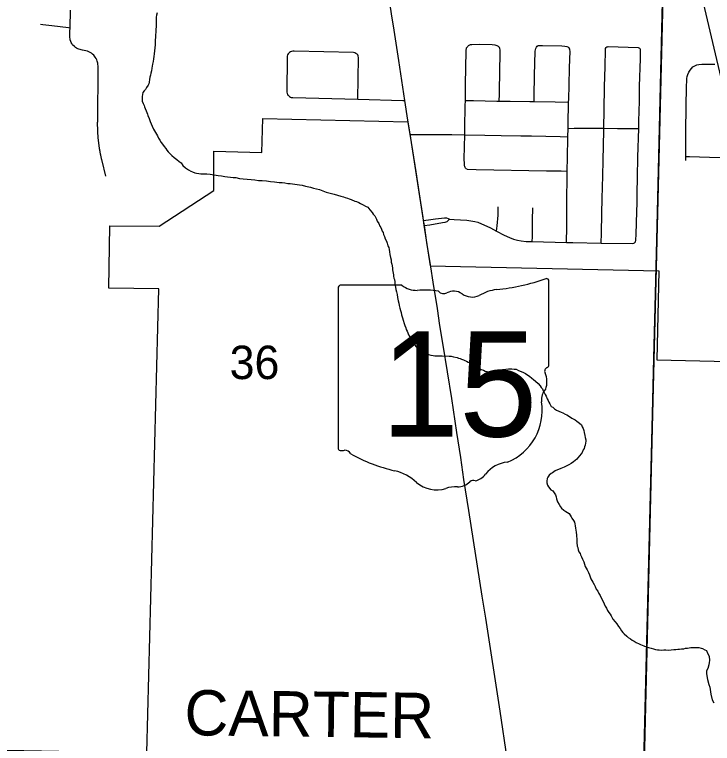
# Model space of a CAD drawing. Extents: x 0 to 34, y 0 to 22.
# Drawn here: x 6.597 to 7.471, y 16.393 to 17.306 of the extents above; entities that cross this region are included whole.
import ezdxf

# ---------------------------------------------------------------- set-up
doc = ezdxf.new("R2010")
doc.units = 0
for name, color, linetype in [('Default', 7, 'Continuous'), ('GM_X_City_Street', 7, 'Continuous'), ('GM_X_County_Road_Text', 7, 'Continuous'), ('GM_X_Minor_River', 7, 'Continuous'), ('GM_X_Rail_Line', 7, 'Continuous'), ('GM_X_Section', 7, 'Continuous'), ('GM_X_Section_Text', 7, 'Continuous'), ('GM_X_State_Location', 7, 'Continuous'), ('GM_X_State_Route', 7, 'Continuous'), ('GM_X_State_Shield', 7, 'Continuous'), ('GM_X_Township_Road', 7, 'Continuous')]:
    doc.layers.add(name, color=color, linetype=linetype)

msp = doc.modelspace()

# ---------------------------------------------------------------- linework, layer by layer
at = {"layer": 'Default'}
msp.add_lwpolyline([(6.62511, 15.83621), (6.63591, 16.30343), (6.54257, 16.30557), (6.54257, 16.38549), (6.7626, 16.3814), (6.7778, 16.96235), (6.71516, 16.96317), (6.7165, 17.04135), (6.77819, 17.04108), (6.84668, 17.08571), (6.84666, 17.13495), (6.90683, 17.13323), (6.90779, 17.17565), (7.08937, 17.17153), (7.09183, 17.15641), (7.10858, 17.04866), (7.10953, 17.04219), (7.11751, 16.99147), (7.40369, 16.98523), (7.40131, 16.87363), (7.61677, 16.86855)], dxfattribs=at)
at = {"layer": 'GM_X_City_Street'}
for p, q in [((7.28989, 17.15306), (7.29007, 17.16342)), ((7.24529, 17.02176), (7.28814, 17.0207)), ((7.33164, 17.01974), (7.37069, 17.01934))]:
    msp.add_line(p, q, dxfattribs=at)
for points in [[(6.71138, 17.10379), (6.70661, 17.12294), (6.70644, 17.1236), (6.70629, 17.12426), (6.70613, 17.12491), (6.70598, 17.12557), (6.70583, 17.12623), (6.70569, 17.12689), (6.70554, 17.12755), (6.70539, 17.12821), (6.70525, 17.12887), (6.70511, 17.12953), (6.70498, 17.13019), (6.70485, 17.13085), (6.70472, 17.13151), (6.70459, 17.13218), (6.70446, 17.13284), (6.70433, 17.1335), (6.70421, 17.13416), (6.70409, 17.13483), (6.70398, 17.13549), (6.70386, 17.13616), (6.70375, 17.13682), (6.70364, 17.13749), (6.70353, 17.13816), (6.70342, 17.13882), (6.70332, 17.13949), (6.70322, 17.14016), (6.70312, 17.14083), (6.70303, 17.1415), (6.70293, 17.14216), (6.70284, 17.14283), (6.70275, 17.1435), (6.70267, 17.14417), (6.70258, 17.14484), (6.7025, 17.14551), (6.70242, 17.14618), (6.70234, 17.14685), (6.70227, 17.14752), (6.70219, 17.14819), (6.70213, 17.14887), (6.70206, 17.14954), (6.70199, 17.15021), (6.70193, 17.15088), (6.70186, 17.15155), (6.70181, 17.15222), (6.70175, 17.1529), (6.7017, 17.15357), (6.70165, 17.15424), (6.7016, 17.15492), (6.70155, 17.15559), (6.70151, 17.15626), (6.70147, 17.15694), (6.70143, 17.15761), (6.70139, 17.15829), (6.70136, 17.15896), (6.70132, 17.15963), (6.7013, 17.16031), (6.70127, 17.16098), (6.70124, 17.16165), (6.70122, 17.16233), (6.70121, 17.16301), (6.70119, 17.16368), (6.70117, 17.16436), (6.70116, 17.16503), (6.70115, 17.16571), (6.70114, 17.16638), (6.70113, 17.16705), (6.70113, 17.16773), (6.70113, 17.1684), (6.70113, 17.16908), (6.70114, 17.16976), (6.70114, 17.17043), (6.70115, 17.1711), (6.70116, 17.17178), (6.70173, 17.24012), (6.70139, 17.24494), (6.70071, 17.24781), (6.70009, 17.24938), (6.69925, 17.251), (6.69821, 17.25254), (6.69719, 17.2539), (6.69616, 17.2551), (6.69468, 17.25645), (6.69335, 17.25748), (6.6918, 17.25852), (6.69011, 17.25935), (6.68857, 17.25995), (6.68203, 17.2615), (6.67772, 17.26268), (6.67612, 17.26318), (6.67475, 17.26369), (6.67331, 17.26463), (6.67204, 17.26585), (6.66974, 17.26822), (6.6687, 17.26965), (6.66801, 17.27103), (6.66742, 17.27229), (6.66689, 17.27412), (6.66656, 17.27553), (6.6664, 17.27735), (6.6665, 17.2849), (6.66662, 17.28949), (6.66716, 17.31162)], [(6.62962, 17.29391), (6.63269, 17.29365), (6.64364, 17.29232), (6.6646, 17.28974), (6.66662, 17.28949)], [(7.02704, 17.19984), (7.02784, 17.25183), (7.02739, 17.25409), (7.02687, 17.25537), (7.02606, 17.25637), (7.02455, 17.25733), (7.02294, 17.25802), (7.02132, 17.25826), (6.94697, 17.2603), (6.94535, 17.26018), (6.94385, 17.25977), (6.94253, 17.2592), (6.94125, 17.25833), (6.93964, 17.25688), (6.93877, 17.25538), (6.93848, 17.25394), (6.93835, 17.25255), (6.93794, 17.20874), (6.93828, 17.20726), (6.93869, 17.20627), (6.9394, 17.20518), (6.93989, 17.20444), (6.94123, 17.20329), (6.94237, 17.20251), (6.9435, 17.20215), (6.94532, 17.20194), (7.02704, 17.19984), (7.08334, 17.19838), (7.08547, 17.19833)], [(7.16147, 17.19835), (7.16172, 17.21837), (7.16236, 17.26036), (7.16246, 17.26207), (7.16271, 17.26314), (7.163, 17.26411), (7.16363, 17.26523)], [(7.20392, 17.19753), (7.2042, 17.20638), (7.20484, 17.23855), (7.20507, 17.25401), (7.20499, 17.2616), (7.20458, 17.26341), (7.20406, 17.26453), (7.20287, 17.26591), (7.20132, 17.26687), (7.19894, 17.26755), (7.19521, 17.26789), (7.17967, 17.26834), (7.16965, 17.26821), (7.16851, 17.26806), (7.16757, 17.26786), (7.16672, 17.26757), (7.16582, 17.26722), (7.16505, 17.26677), (7.16438, 17.26612), (7.16363, 17.26523)], [(7.24768, 17.19692), (7.24776, 17.2039), (7.24806, 17.2299), (7.24834, 17.24482), (7.24885, 17.26023), (7.24911, 17.26199), (7.2497, 17.26365), (7.25041, 17.26525), (7.25157, 17.2664), (7.2528, 17.26706), (7.25427, 17.26731), (7.25579, 17.26743), (7.25823, 17.26739), (7.28244, 17.26673), (7.28609, 17.26649), (7.28838, 17.26606), (7.28989, 17.26545), (7.29107, 17.26448), (7.29191, 17.26309)], [(7.29075, 17.19612), (7.29082, 17.19995), (7.29138, 17.21735), (7.29199, 17.23911), (7.29259, 17.26014), (7.29241, 17.26179), (7.29191, 17.26309)], [(7.33484, 17.16367), (7.33532, 17.18673), (7.33584, 17.21529), (7.33647, 17.24074), (7.33675, 17.26182), (7.33704, 17.26344), (7.33774, 17.26478), (7.33842, 17.2654), (7.33924, 17.26573), (7.34027, 17.26583), (7.37771, 17.2646), (7.37861, 17.26436), (7.37946, 17.26376)], [(7.37857, 17.16335), (7.37883, 17.17262), (7.37934, 17.19749), (7.37958, 17.21615), (7.38056, 17.25033), (7.38067, 17.26089), (7.38061, 17.26211), (7.38015, 17.26302), (7.37946, 17.26376)], [(7.43737, 17.12319), (7.43735, 17.12828), (7.43741, 17.1575), (7.43796, 17.19279), (7.43839, 17.2133), (7.4389, 17.22575), (7.43919, 17.22831), (7.43983, 17.23079), (7.44114, 17.23383), (7.44297, 17.2365), (7.44454, 17.2386), (7.44646, 17.24043), (7.44869, 17.24188), (7.45111, 17.24292), (7.45365, 17.24358), (7.45747, 17.24397), (7.47371, 17.24389)], [(7.16088, 17.15544), (7.16097, 17.16427), (7.16139, 17.19163), (7.16147, 17.19835)], [(7.16147, 17.19835), (7.16715, 17.19825), (7.17149, 17.19817), (7.20068, 17.19756), (7.20392, 17.19753)], [(7.20392, 17.19753), (7.21743, 17.1974), (7.24227, 17.197), (7.24768, 17.19692)], [(7.24768, 17.19692), (7.27393, 17.19651), (7.29075, 17.19612)], [(7.29007, 17.16342), (7.29015, 17.16825), (7.29075, 17.19612)], [(7.29007, 17.16342), (7.29771, 17.16355), (7.3156, 17.16362), (7.33484, 17.16367)], [(7.33164, 17.01974), (7.33182, 17.03219), (7.33226, 17.05693), (7.33283, 17.07556), (7.33349, 17.10416), (7.33388, 17.12337), (7.33477, 17.16063), (7.33484, 17.16367)], [(7.33484, 17.16367), (7.3519, 17.16345), (7.36937, 17.16344), (7.37857, 17.16335)], [(7.37069, 17.01934), (7.3725, 17.01961), (7.37339, 17.02019), (7.3743, 17.02148), (7.37483, 17.02364), (7.3752, 17.03092), (7.37608, 17.05886), (7.37637, 17.07005), (7.37654, 17.08186), (7.37707, 17.10238), (7.37753, 17.12725), (7.37857, 17.16335)], [(7.09207, 17.15586), (7.10017, 17.15584), (7.12452, 17.15578), (7.14467, 17.15571), (7.16088, 17.15544)], [(7.16366, 17.11239), (7.16262, 17.11279), (7.16176, 17.1136), (7.16117, 17.11454), (7.16066, 17.11556), (7.1604, 17.1166), (7.1602, 17.11896), (7.16012, 17.12511), (7.16088, 17.15544)], [(7.16088, 17.15544), (7.18571, 17.15494), (7.20622, 17.15471), (7.23109, 17.1543), (7.24414, 17.15415), (7.2802, 17.15333), (7.28989, 17.15306)], [(7.28903, 17.10984), (7.28954, 17.12724), (7.28987, 17.15147), (7.28989, 17.15306)], [(7.43735, 17.12828), (7.44229, 17.12814), (7.46718, 17.12748), (7.49768, 17.12664), (7.51408, 17.12609), (7.53067, 17.12553), (7.55309, 17.12484), (7.58855, 17.12405), (7.59528, 17.12382)], [(7.16366, 17.11239), (7.17484, 17.11184), (7.26324, 17.11032), (7.28129, 17.11007), (7.28903, 17.10984)], [(7.28814, 17.0207), (7.28835, 17.03998), (7.28843, 17.05824), (7.28838, 17.07439), (7.2888, 17.10183), (7.28903, 17.10984)], [(7.20044, 17.03484), (7.20138, 17.04141), (7.20253, 17.0549), (7.20266, 17.06536)], [(7.24529, 17.02176), (7.24537, 17.02772), (7.24563, 17.04839), (7.24601, 17.06405)], [(7.10882, 17.0481), (7.11552, 17.04902), (7.12425, 17.05022), (7.13174, 17.05116), (7.13524, 17.05153), (7.13779, 17.05137), (7.13976, 17.05071), (7.14174, 17.04956)], [(7.10977, 17.04164), (7.11719, 17.04284), (7.1329, 17.04538), (7.13615, 17.04602), (7.13853, 17.04701), (7.14009, 17.04817), (7.14174, 17.04956)], [(7.14174, 17.04956), (7.14763, 17.04928), (7.16331, 17.04832), (7.16833, 17.04783), (7.17331, 17.04697), (7.17699, 17.04596), (7.19296, 17.03873), (7.20044, 17.03484)], [(7.20044, 17.03484), (7.21004, 17.02984), (7.21677, 17.02679), (7.22194, 17.02488), (7.22667, 17.0236), (7.23147, 17.0227), (7.23761, 17.02196), (7.24529, 17.02176)], [(7.28814, 17.0207), (7.29596, 17.02051), (7.33164, 17.01974)]]:
    msp.add_lwpolyline(points, dxfattribs=at)
at = {"layer": 'GM_X_Minor_River'}
for points in [[(6.77546, 17.30804), (6.775, 17.30539), (6.77454, 17.30274), (6.77447, 17.30009), (6.77439, 17.29743), (6.77427, 17.29325), (6.77419, 17.29059), (6.7741, 17.28755), (6.77401, 17.28413), (6.77353, 17.28072), (6.77343, 17.2773), (6.77334, 17.27426), (6.77325, 17.27122), (6.77316, 17.26818), (6.77207, 17.25681), (6.77159, 17.2534), (6.77113, 17.25037), (6.77066, 17.24734), (6.7698, 17.24394), (6.76935, 17.2413), (6.7689, 17.23903), (6.76842, 17.23562), (6.76757, 17.2326), (6.76712, 17.22995), (6.76667, 17.22768), (6.7662, 17.22466), (6.76573, 17.22125), (6.76529, 17.21936), (6.76448, 17.21748), (6.76249, 17.2145), (6.76091, 17.21226), (6.75933, 17.2104), (6.75775, 17.20817), (6.7573, 17.2059), (6.75685, 17.20325), (6.75677, 17.20059), (6.75706, 17.19754), (6.75811, 17.19447), (6.75918, 17.19216), (6.75989, 17.19024), (6.76059, 17.18831), (6.76202, 17.18523), (6.76273, 17.18331), (6.76343, 17.18139), (6.76413, 17.17947), (6.76555, 17.17601), (6.76696, 17.17216), (6.76801, 17.16909), (6.76944, 17.16601), (6.77086, 17.16255), (6.77593, 17.15403), (6.77737, 17.15133), (6.77881, 17.14863), (6.78063, 17.14591), (6.78246, 17.14358), (6.78428, 17.14087), (6.78649, 17.13814), (6.78795, 17.1362), (6.78941, 17.13425), (6.79199, 17.13152), (6.79383, 17.12956), (6.79679, 17.12682), (6.80014, 17.12444), (6.80311, 17.12207), (6.80571, 17.1201), (6.8079, 17.11699), (6.81123, 17.11385), (6.81496, 17.11147), (6.81795, 17.10986), (6.81983, 17.10904)], [(6.81983, 17.10904), (6.82283, 17.10782), (6.82471, 17.10738), (6.82774, 17.10691), (6.83039, 17.10646), (6.83266, 17.10639), (6.83494, 17.10633), (6.83799, 17.10662), (6.84215, 17.10612), (6.84706, 17.10522), (6.85197, 17.10432), (6.85614, 17.10382), (6.8603, 17.10332), (6.87089, 17.10187), (6.87431, 17.10177), (6.87884, 17.10088), (6.88339, 17.10037), (6.88831, 17.09985), (6.89323, 17.09933), (6.89777, 17.09882), (6.90232, 17.09831), (6.90725, 17.09816), (6.91255, 17.09763), (6.91748, 17.09711), (6.9224, 17.09659), (6.92845, 17.09565), (6.93225, 17.09554), (6.93565, 17.09506), (6.93905, 17.09459), (6.94209, 17.0945), (6.94511, 17.09403), (6.94814, 17.09356), (6.95078, 17.09311), (6.95381, 17.09264), (6.95721, 17.09216), (6.96137, 17.09128), (6.96741, 17.08997), (6.97117, 17.08872), (6.97494, 17.08785), (6.97871, 17.08698), (6.98285, 17.08534), (6.98736, 17.08369), (6.99226, 17.08241), (6.99716, 17.08113), (7.0013, 17.07987), (7.00544, 17.07861), (7.00883, 17.07775), (7.01109, 17.07692), (7.0141, 17.07608), (7.01598, 17.07526), (7.01861, 17.07443), (7.02311, 17.0724), (7.025, 17.07196), (7.028, 17.07073), (7.03025, 17.06953), (7.03361, 17.06753), (7.0366, 17.06592), (7.03922, 17.06471), (7.04179, 17.06159), (7.04473, 17.05809), (7.04619, 17.05614), (7.04802, 17.05381), (7.04947, 17.05149), (7.05018, 17.04956), (7.05125, 17.04725), (7.05306, 17.04416), (7.05449, 17.04107), (7.05557, 17.03914), (7.05666, 17.03721), (7.05735, 17.03491), (7.05843, 17.03298), (7.05913, 17.03068), (7.06019, 17.02798), (7.06124, 17.02491), (7.06268, 17.02221), (7.06374, 17.01952), (7.06441, 17.01645), (7.06549, 17.01414), (7.06618, 17.01184), (7.06647, 17.00879), (7.06713, 17.00535), (7.06779, 17.00191), (7.06846, 16.99885), (7.06875, 16.9958), (7.06944, 16.9935), (7.06976, 16.99121), (7.07006, 16.98854), (7.07037, 16.98624), (7.0707, 16.98434), (7.07101, 16.98204), (7.07134, 16.98013), (7.07166, 16.97822), (7.07197, 16.97593), (7.07268, 16.97401), (7.07298, 16.97134), (7.0733, 16.96943), (7.0746, 16.96179), (7.07527, 16.95873), (7.07593, 16.95529), (7.07658, 16.95147), (7.07723, 16.94764)], [(7.07723, 16.94764), (7.07828, 16.94457), (7.07857, 16.94152), (7.07924, 16.93846), (7.08029, 16.93539), (7.08098, 16.93271), (7.08166, 16.93003), (7.08268, 16.9262), (7.08373, 16.92312), (7.08476, 16.91929), (7.08583, 16.9166), (7.08688, 16.91353), (7.08758, 16.9116), (7.08865, 16.90929), (7.08936, 16.90737), (7.09043, 16.90506), (7.09151, 16.90313), (7.09255, 16.89967), (7.09476, 16.89733), (7.09585, 16.8954), (7.09768, 16.89306), (7.0995, 16.89035), (7.10207, 16.88723), (7.10467, 16.88526), (7.10727, 16.88328), (7.11027, 16.88206), (7.11366, 16.88082), (7.11554, 16.88038), (7.11818, 16.87955), (7.1212, 16.87908), (7.12347, 16.87863), (7.12688, 16.87854), (7.12878, 16.87848), (7.13259, 16.87875), (7.1413, 16.87812), (7.14358, 16.87805), (7.1466, 16.87721), (7.15113, 16.87632), (7.15301, 16.87588), (7.1549, 16.87545), (7.15678, 16.87463), (7.15902, 16.87343), (7.1609, 16.87261), (7.16277, 16.8718), (7.16502, 16.87059), (7.16689, 16.86978), (7.17025, 16.86778), (7.17247, 16.86582), (7.17622, 16.86419), (7.17922, 16.86258), (7.18146, 16.86138), (7.1841, 16.86054), (7.18634, 16.85933), (7.1886, 16.85889), (7.19125, 16.85843), (7.1939, 16.85798), (7.19654, 16.85752), (7.19922, 16.8582), (7.20152, 16.8589), (7.20344, 16.8596), (7.20613, 16.86066), (7.20843, 16.86136), (7.21225, 16.86201), (7.21567, 16.86229), (7.21795, 16.86223), (7.21985, 16.86217), (7.2225, 16.86209), (7.22516, 16.86202), (7.22815, 16.86041), (7.2334, 16.85798), (7.23677, 16.85636), (7.23864, 16.85517), (7.24162, 16.85318), (7.24459, 16.85081), (7.24681, 16.84885), (7.24941, 16.84687), (7.25275, 16.84411), (7.25532, 16.841), (7.2564, 16.83907), (7.25786, 16.83712), (7.25893, 16.83481), (7.26002, 16.83288), (7.26146, 16.83018), (7.26254, 16.82824), (7.26396, 16.82478), (7.26505, 16.82285), (7.26612, 16.82054), (7.2672, 16.8186), (7.269, 16.81513), (7.27088, 16.81431), (7.2731, 16.81235), (7.27571, 16.81075), (7.27832, 16.80916), (7.28132, 16.80793), (7.28358, 16.8071), (7.28657, 16.8055), (7.28845, 16.80468), (7.29293, 16.80189), (7.29479, 16.8007), (7.29665, 16.7995), (7.2989, 16.7983)], [(7.2989, 16.7983), (7.30113, 16.79671), (7.30448, 16.79434), (7.30669, 16.79199), (7.30776, 16.78968), (7.30885, 16.78775), (7.30991, 16.78506), (7.31022, 16.78276), (7.31087, 16.77894), (7.31155, 16.77626), (7.31223, 16.77358), (7.31218, 16.77168), (7.31172, 16.76903), (7.31128, 16.76676), (7.31045, 16.76451), (7.31002, 16.76262), (7.30882, 16.76075), (7.3076, 16.75774), (7.3064, 16.75588), (7.30443, 16.75327), (7.30246, 16.75105), (7.30089, 16.74919), (7.297, 16.74588), (7.2939, 16.74369), (7.29082, 16.74226), (7.28772, 16.74045), (7.28503, 16.73938), (7.2831, 16.7383), (7.28118, 16.73759), (7.27388, 16.73438), (7.27077, 16.73219), (7.26884, 16.7311), (7.26651, 16.72927), (7.26454, 16.72666), (7.26372, 16.72479), (7.26363, 16.72175), (7.26357, 16.71947), (7.26425, 16.71679), (7.2657, 16.71446), (7.26864, 16.71096), (7.27087, 16.70937), (7.2727, 16.70704), (7.27414, 16.70433), (7.27521, 16.70202), (7.27552, 16.69935), (7.27694, 16.69589), (7.27874, 16.69241), (7.28056, 16.6897), (7.28164, 16.68777), (7.28461, 16.6854), (7.28722, 16.68381), (7.28947, 16.6826), (7.29132, 16.68103), (7.29387, 16.67715), (7.29495, 16.67522), (7.29677, 16.6725), (7.29822, 16.67018), (7.29855, 16.66827), (7.29885, 16.6656), (7.29953, 16.66292), (7.30014, 16.65796), (7.30042, 16.65415), (7.30074, 16.65224), (7.30105, 16.64995), (7.30096, 16.64691), (7.3009, 16.64463), (7.30154, 16.64043), (7.30224, 16.63851), (7.30254, 16.63584), (7.3036, 16.63314), (7.30507, 16.6312), (7.30577, 16.62928), (7.30685, 16.62697), (7.30827, 16.62388), (7.30969, 16.62042), (7.31143, 16.61467), (7.31396, 16.61041), (7.31577, 16.60732), (7.31682, 16.60425), (7.31857, 16.59925), (7.32111, 16.595), (7.32293, 16.59228), (7.32399, 16.58959), (7.32542, 16.58651), (7.32724, 16.5838), (7.32868, 16.58109), (7.33012, 16.57839), (7.33514, 16.56798), (7.33658, 16.56527), (7.33802, 16.56257), (7.33946, 16.55987), (7.34128, 16.55715), (7.34275, 16.55521), (7.34382, 16.5529), (7.34599, 16.54903), (7.34892, 16.54553), (7.35112, 16.5428), (7.35331, 16.5397), (7.35513, 16.53698), (7.35695, 16.53427), (7.3588, 16.53231)], [(7.3588, 16.53231), (7.36026, 16.53037), (7.3636, 16.52762), (7.36545, 16.52604), (7.36805, 16.52406), (7.37028, 16.52248), (7.37291, 16.52126), (7.37552, 16.51967), (7.37889, 16.51805), (7.38077, 16.51723), (7.38264, 16.51642), (7.3849, 16.51559), (7.3879, 16.51437), (7.39092, 16.51352), (7.39393, 16.51267), (7.39694, 16.51183), (7.39958, 16.51099), (7.40184, 16.51054), (7.40412, 16.51048), (7.40677, 16.51002), (7.40982, 16.51031), (7.41247, 16.51024), (7.41626, 16.51013), (7.41931, 16.51042), (7.42236, 16.51071), (7.42503, 16.51102), (7.42732, 16.51133), (7.42959, 16.51127), (7.43188, 16.51158), (7.43493, 16.51187), (7.43723, 16.51257), (7.4395, 16.5125), (7.44179, 16.51281), (7.4437, 16.51314), (7.45092, 16.51331), (7.45358, 16.51324), (7.45659, 16.51239), (7.45848, 16.51195), (7.46147, 16.51035), (7.46335, 16.50953), (7.46477, 16.50607), (7.46657, 16.5026), (7.46717, 16.49726), (7.46671, 16.49461), (7.46625, 16.49158), (7.46497, 16.48705), (7.46337, 16.48406), (7.46326, 16.48026), (7.46458, 16.47338), (7.46629, 16.46686), (7.46734, 16.46379), (7.4686, 16.45501), (7.47067, 16.44773), (7.47246, 16.44387)]]:
    msp.add_lwpolyline(points, dxfattribs=at)
at = {"layer": 'GM_X_Rail_Line'}
msp.add_lwpolyline([(8.31912, 14.1), (8.26519, 14.29151), (7.99841, 15.30059), (7.77868, 16.11858), (7.54638, 16.95196), (7.4475, 17.3725), (7.39862, 17.49992), (7.33889, 17.63816), (7.26967, 17.77776), (7.07158, 18.08945), (7.04174, 18.13417), (7.01055, 18.16261), (6.97802, 18.17479), (6.94272, 18.181)], dxfattribs=at)
at = {"layer": 'GM_X_Section'}
for points in [[(6.41184, 17.39355), (7.41005, 17.37616), (7.38494, 16.36973), (6.38559, 16.38675)], [(7.41005, 17.37616), (8.34451, 17.35473), (8.34716, 17.35468), (8.32696, 16.34778), (7.38494, 16.36973)]]:
    msp.add_lwpolyline(points, close=True, dxfattribs=at)
at = {"layer": 'GM_X_State_Route'}
for points in [[(7.05723, 17.38071), (7.05851, 17.37262), (7.06138, 17.35481), (7.06863, 17.30689), (7.07185, 17.28663), (7.07782, 17.24856), (7.08547, 17.19833), (7.08923, 17.17357), (7.08949, 17.17172), (7.08965, 17.17073)], [(7.08965, 17.17073), (7.09207, 17.15586), (7.09411, 17.1433), (7.09941, 17.10894), (7.10373, 17.08134), (7.10827, 17.05187), (7.10882, 17.0481), (7.10977, 17.04164), (7.11287, 17.02055), (7.11752, 16.99235), (7.11775, 16.99092)], [(7.11775, 16.99092), (7.1179, 16.98993), (7.12086, 16.97079), (7.12599, 16.93774)], [(7.12599, 16.93774), (7.12926, 16.91671), (7.13313, 16.89215), (7.14416, 16.82525), (7.15037, 16.78279), (7.15523, 16.75144), (7.1593, 16.72376), (7.16526, 16.68503), (7.18193, 16.5775), (7.18657, 16.54989), (7.20458, 16.43373), (7.21343, 16.3743)]]:
    msp.add_lwpolyline(points, dxfattribs=at)
at = {"layer": 'GM_X_State_Shield'}
for p, q in [((7.26597, 16.86723), (7.26597, 16.97192)), ((7.0023, 16.96351), (7.0023, 16.76339)), ((7.08211, 16.96696), (7.0049, 16.96696)), ((7.26594, 16.86726), (7.26597, 16.86723))]:
    msp.add_line(p, q, dxfattribs=at)
for centre, radius, start, end in [((7.17204, 17.23979), 0.27962, 275.84447, 288.90645), ((7.26304, 16.97235), 0.00294, 351.86209, 97.738), ((7.00532, 16.96394), 0.00305, 98.1301, 188.1301), ((7.1005, 16.99019), 0.02963, 231.61951, 271.11188), ((7.11032, 16.85461), 0.10636, 80.48669, 94.98827), ((7.13447, 16.96498), 0.00855, 219.79206, 297.10237), ((7.14702, 16.94185), 0.01777, 54.46668, 119.14113), ((7.20771, 16.90583), 0.05625, 97.34618, 120.76885), ((7.16996, 16.97357), 0.02138, 233.85621, 294.82819), ((7.26529, 16.85955), 0.00454, 107.94398, 210.33697), ((7.26283, 16.86683), 0.00314, 289.60381, 7.73413), ((7.23639, 16.84631), 0.02727, 340.03296, 23.64957), ((7.27648, 16.82342), 0.01984, 136.8065, 186.92959), ((7.18771, 16.8101), 0.06994, 292.30889, 8.98584), ((7.00535, 16.76296), 0.00308, 171.95839, 258.30661), ((7.00581, 16.78343), 0.02352, 267.33899, 280.60386), ((7.01063, 16.75185), 0.00848, 29.74838, 93.27175), ((7.11769, 16.93165), 0.20192, 240.41292, 257.1985), ((7.2172, 16.70721), 0.0383, 94.40312, 142.57675), ((7.05749, 16.67349), 0.06318, 47.18416, 75.83597), ((7.16867, 16.744), 0.0226, 282.87319, 323.27711), ((7.17123, 16.71649), 0.00601, 65.75173, 132.64842), ((7.12582, 16.75086), 0.04009, 230.70037, 286.29184), ((7.14898, 16.68167), 0.03294, 85.69512, 111.20995), ((7.15191, 16.73587), 0.02136, 268.77702, 315.54927)]:
    msp.add_arc(centre, radius, start, end, dxfattribs=at)
at = {"layer": 'GM_X_Township_Road'}
for points in [[(7.37669, 15.31551), (7.38543, 16.36959), (7.39749, 16.87556), (7.40018, 16.98823), (7.40941, 17.37521)], [(7.40941, 17.37521), (7.40018, 16.98823), (7.39749, 16.87556), (7.38543, 16.36959), (8.33159, 16.35046)]]:
    msp.add_lwpolyline(points, dxfattribs=at)

# ---------------------------------------------------------------- texts
at = {"layer": 'GM_X_County_Road_Text'}
msp.add_text('CARTER', height=0.056818, rotation=359.30315, dxfattribs=at).set_placement((6.80958, 16.40344))
at = {"layer": 'GM_X_Section_Text'}
msp.add_text('36', height=0.041856, rotation=0.00001, dxfattribs=at).set_placement((6.86639, 16.84948))
at = {"layer": 'GM_X_State_Location'}
for s, p in [('s', (7.13116, 16.85015)), ('r', (7.13115, 16.85015))]:
    msp.add_text(s, height=0.000189, dxfattribs=at).set_placement(p)
msp.add_text('15', height=0.000189, rotation=0.00001, dxfattribs=at).set_placement((7.08347, 16.83637))
at = {"layer": 'GM_X_State_Shield'}
msp.add_text('15', height=0.131836, dxfattribs=at).set_placement((7.05561, 16.77751))

doc.saveas('drawing.dxf')
